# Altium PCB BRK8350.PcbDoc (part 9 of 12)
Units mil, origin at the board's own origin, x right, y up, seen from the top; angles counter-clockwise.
Board outline 9448.82 x 5905.51 mil, 8 copper layers (L1-TOP, L2-GND, L3-SIG, L4-GND, L5-PWR, L6-PWR, L7-GND, L8-BOT), stack 57.69 mil thick; 288 components, 543 nets, 1891 pads, 2032 vias.
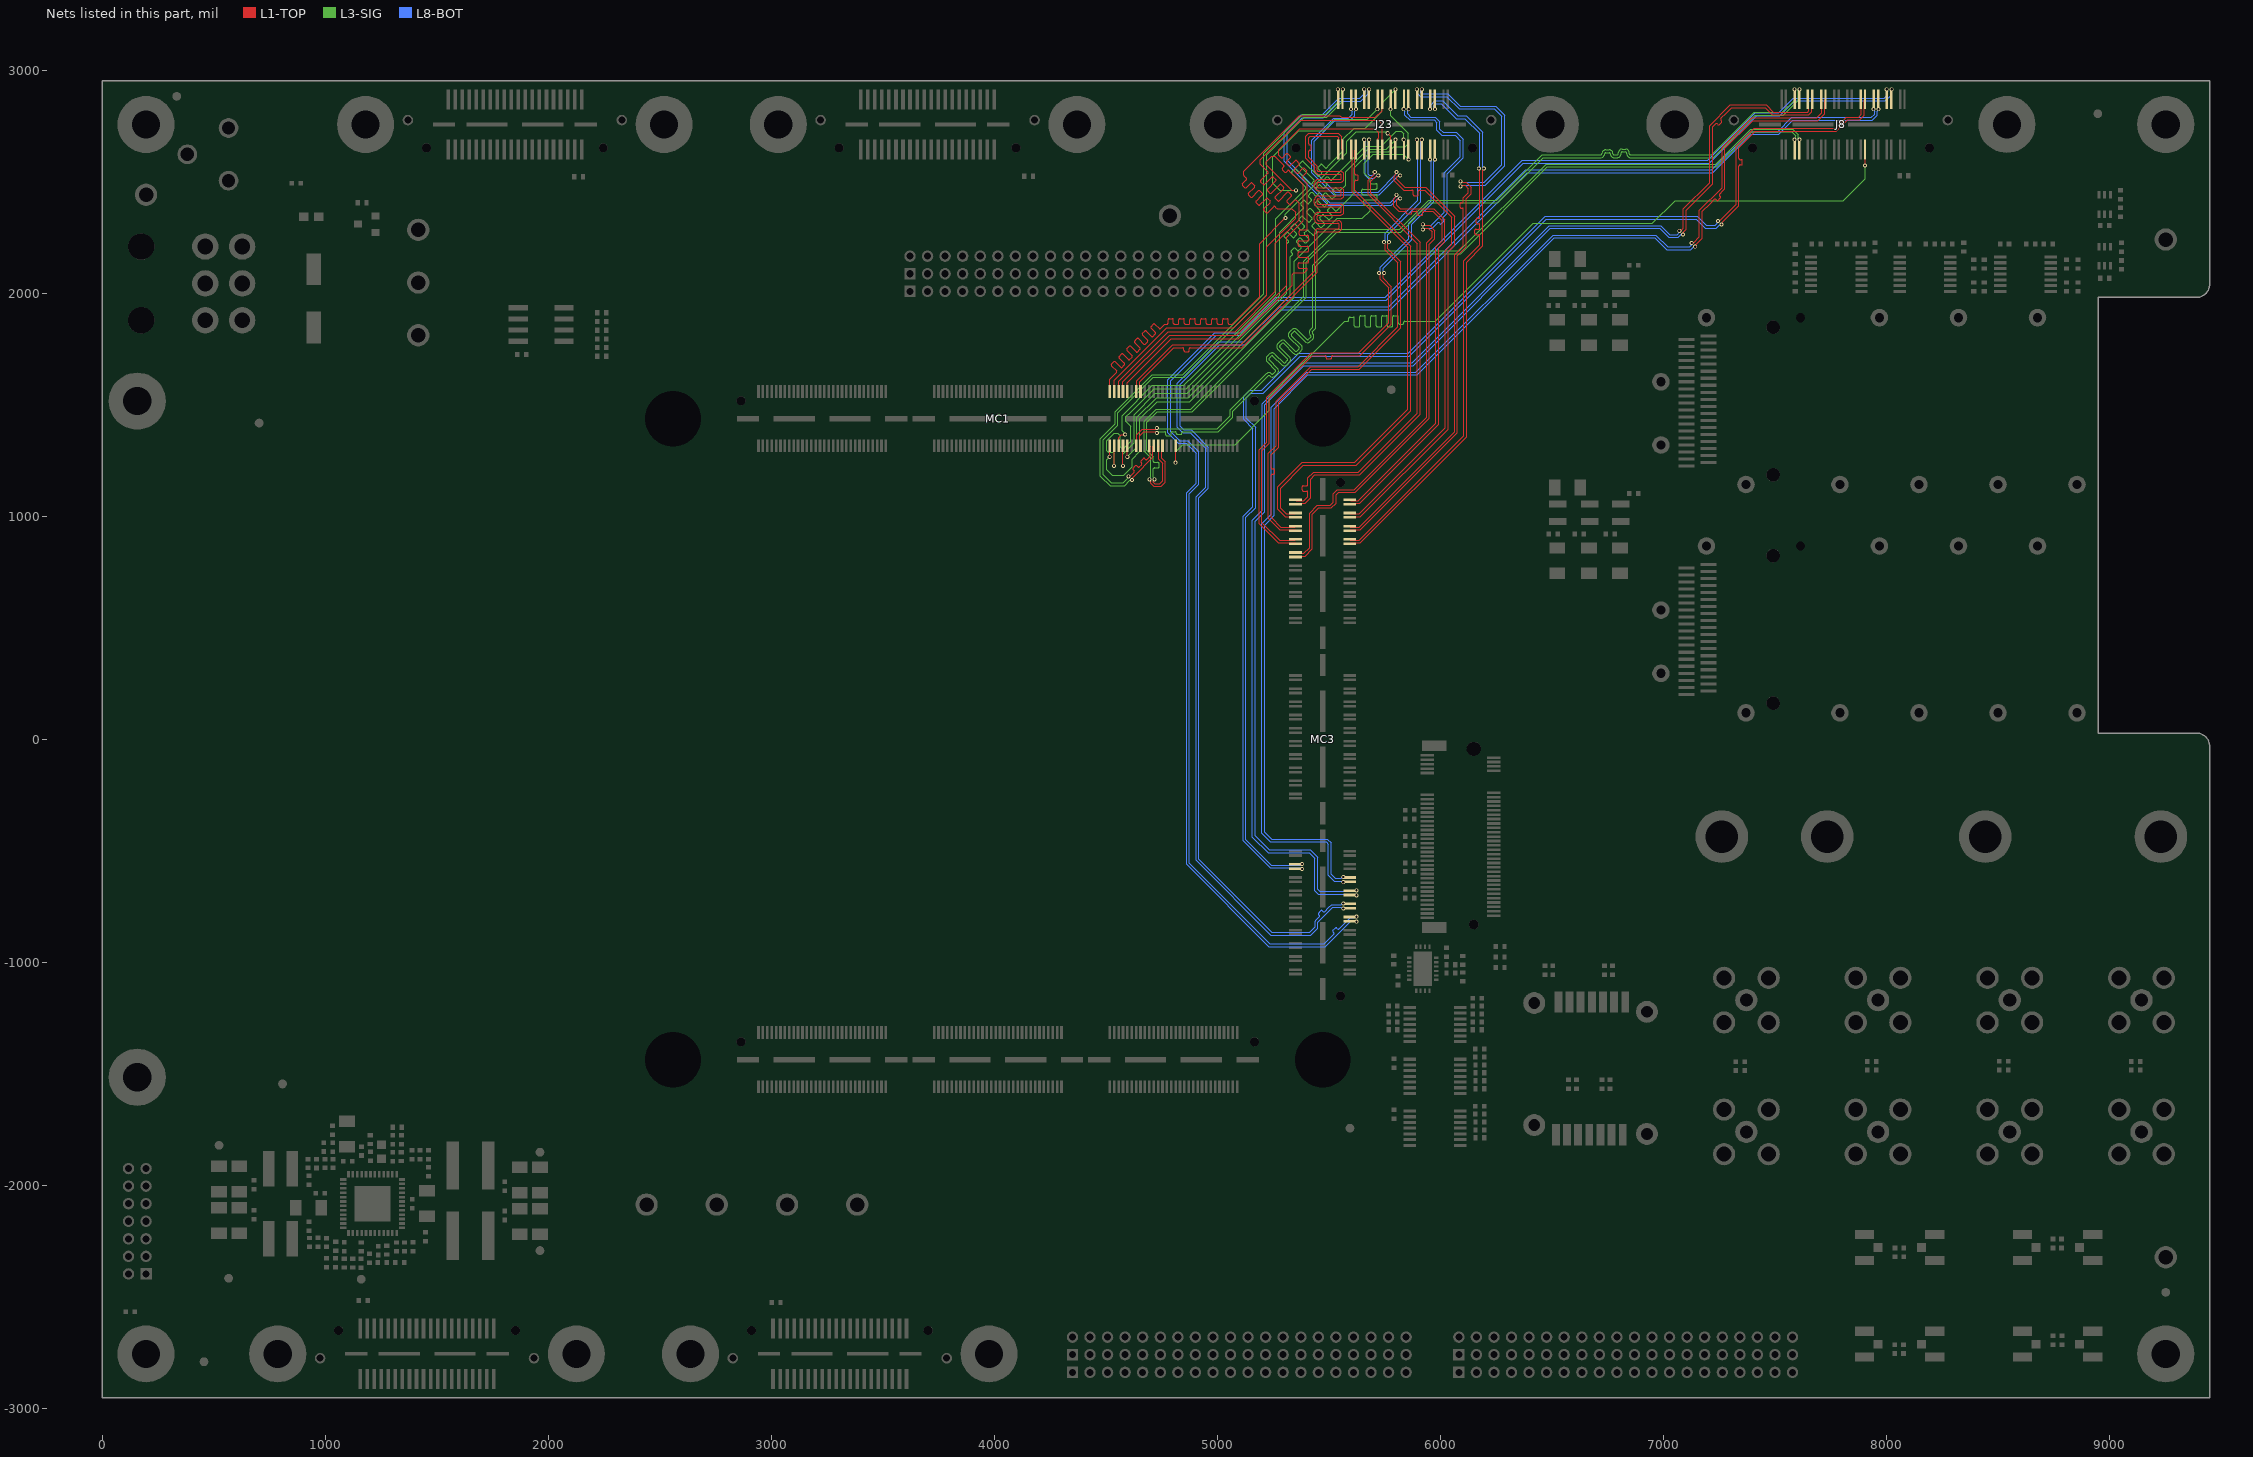
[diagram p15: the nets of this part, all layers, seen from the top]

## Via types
v1: diameter 18, hole 10, L1-TOP to L8-BOT, tented both sides, 2032 vias

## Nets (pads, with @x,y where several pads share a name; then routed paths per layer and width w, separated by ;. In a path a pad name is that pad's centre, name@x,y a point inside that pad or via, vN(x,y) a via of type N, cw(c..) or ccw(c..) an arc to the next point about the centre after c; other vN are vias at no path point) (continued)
PORTE_C2P_CLKN: J23.36 MC1.135 | length 2762.6
  L1-TOP w4.2: MC1.135@4655.53,1558.68 4651.98,1562.22 4651.98,1602.36 4701.98,1652.35 4759.06,1709.44 4804.76,1755.14 4818.81,1755.14 4845.11,1755.14 cw(c4845.11,1750.3) 4849.95,1750.3 4849.95,1742.6 ccw(c4854.79,1742.6) 4854.79,1737.76 4869.31,1737.76 ccw(c4869.31,1742.6) 4874.15,1742.6 4874.15,1750.3 cw(c4878.99,1750.3) 4878.99,1755.14 4895.59,1755.14 5109.74,1755.14 5448.62,2094.02 5448.62,2114.17 5448.62,2270.96 cw(c5453.46,2270.96) 5453.46,2275.8 5540.81,2275.8 ccw(c5540.81,2293.24) 5558.25,2293.24 5558.25,2307.76 ccw(c5540.81,2307.76) 5540.81,2325.2 5452.99,2325.2 cw(c5452.99,2330.04) 5448.15,2330.04 5448.15,2344.56 cw(c5452.99,2344.56) 5452.99,2349.4 5550.27,2349.4 ccw(c5550.27,2366.84) 5567.71,2366.84 5567.71,2381.36 ccw(c5550.27,2381.36) 5550.27,2398.8 5452.99,2398.8 cw(c5452.99,2403.64) 5448.15,2403.64 5448.15,2418.16 cw(c5452.99,2418.16) 5452.99,2423 5550.27,2423 ccw(c5550.27,2440.44) 5567.71,2440.44 5567.71,2454.96 ccw(c5550.27,2454.96) 5550.27,2472.4 5452.99,2472.4 cw(c5452.99,2477.24) 5448.15,2477.24 5448.15,2491.76 cw(c5452.99,2491.76) 5452.99,2496.6 5550.27,2496.6 ccw(c5550.27,2514.04) 5567.71,2514.04 5567.71,2528.56 ccw(c5550.27,2528.56) 5550.27,2546 5453.46,2546 cw(c5453.46,2550.84) 5448.62,2550.84 5448.62,2559.24 5448.62,2569.41 5409.45,2608.58 5409.45,2634.88 cw(c5414.29,2634.88) 5414.29,2639.72 5416.42,2639.72 ccw(c5416.42,2644.56) 5421.26,2644.56 5421.26,2659.08 ccw(c5416.42,2659.08) 5416.42,2663.92 5414.29,2663.92 cw(c5414.29,2668.76) 5409.45,2668.76 5409.45,2689.78 5409.45,2697.27 5415.92,2703.74 5537.2,2703.74 5545.04,2695.91 5545.04,2688.08 5544.91,2687.95 5544.91,2646.44 J23.36@5541.5,2643.03
PORTE_C2P_CLKP: J23.34 MC1.133 | length 2762.6
  L1-TOP w4.2: MC1.133@4635.84,1558.68 4639.38,1562.22 4639.38,1607.58 4799.54,1767.74 5104.52,1767.74 5436.02,2099.24 5436.02,2114.17 5436.02,2270.96 cw(c5453.46,2270.96) 5453.46,2288.4 5540.81,2288.4 ccw(c5540.81,2293.24) 5545.65,2293.24 5545.65,2307.76 ccw(c5540.81,2307.76) 5540.81,2312.6 5452.99,2312.6 cw(c5452.99,2330.04) 5435.55,2330.04 5435.55,2344.56 cw(c5452.99,2344.56) 5452.99,2362 5550.27,2362 ccw(c5550.27,2366.84) 5555.11,2366.84 5555.11,2381.36 ccw(c5550.27,2381.36) 5550.27,2386.2 5452.99,2386.2 cw(c5452.99,2403.64) 5435.55,2403.64 5435.55,2418.16 cw(c5452.99,2418.16) 5452.99,2435.6 5550.27,2435.6 ccw(c5550.27,2440.44) 5555.11,2440.44 5555.11,2454.96 ccw(c5550.27,2454.96) 5550.27,2459.8 5452.99,2459.8 cw(c5452.99,2477.24) 5435.55,2477.24 5435.55,2491.76 cw(c5452.99,2491.76) 5452.99,2509.2 5550.27,2509.2 ccw(c5550.27,2514.04) 5555.11,2514.04 5555.11,2528.56 ccw(c5550.27,2528.56) 5550.27,2533.4 5453.46,2533.4 cw(c5453.46,2550.84) 5436.02,2550.84 5436.02,2559.24 5436.02,2564.19 5396.85,2603.36 5396.85,2702.49 5410.7,2716.34 5542.42,2716.34 5557.64,2701.13 5557.64,2688.08 5557.77,2687.95 5557.77,2646.44 J23.34@5561.18,2643.03
PORTE_P2C_CLKN: J23.35 MC1.142 | length 2684.1
  L1-TOP w4.2: v1(4617.02,1162.51) 4619.66,1165.15 4619.66,1172.15 4628.75,1181.23 4711.04,1263.53 4711.04,1311.83 MC1.142@4714.58,1315.37
  L3-SIG w4.25: v1(4617.02,1162.51) 4614.39,1159.88 4607.43,1159.88 4584.04,1136.49 4518.85,1136.49 4475.54,1179.8 4475.54,1262.21 4475.54,1347.82 4541.34,1413.62 4541.34,1467.81 4687.7,1614.17 4708.37,1634.84 4845.47,1634.84 5208.66,1998.03 5208.66,2625.98 5383.71,2801.04 5421.26,2801.04 5486.08,2801.04 5545.01,2859.97 5545.01,2911.21 5542.52,2913.7 v1(5540.09,2913.7)
PORTE_P2C_CLKP: J23.33 MC1.140 | length 2684.1
  L1-TOP w4.2: v1(4601.11,1178.42) 4603.75,1181.06 4610.75,1181.06 4615.39,1185.69 4625.03,1195.33 4626.51,1196.82 ccw(c4623.09,1200.24) 4626.51,1203.66 4622.36,1207.81 cw(c4625.79,1211.23) 4622.36,1214.65 4632.63,1224.92 cw(c4636.05,1221.5) 4639.48,1224.92 4643.62,1220.77 ccw(c4647.05,1224.19) 4650.47,1220.77 4660.74,1231.04 ccw(c4657.31,1234.46) 4660.74,1237.88 4657.89,1240.73 cw(c4661.31,1244.15) 4657.89,1247.57 4668.16,1257.84 cw(c4671.58,1254.42) 4675,1257.84 4677.85,1255 ccw(c4681.27,1258.42) 4684.69,1255 4691.83,1262.13 4698.44,1268.74 4698.44,1311.83 MC1.140@4694.9,1315.37
  L3-SIG w4.25: v1(4601.11,1178.42) 4598.48,1175.79 4598.48,1168.82 4578.8,1149.14 4524.09,1149.14 4488.19,1185.04 4488.19,1342.58 4553.99,1408.38 4553.99,1462.57 4713.61,1622.19 4850.71,1622.19 5221.31,1992.79 5221.31,2620.74 5388.95,2788.39 5491.31,2788.39 5557.66,2854.73 5557.66,2911.21 5560.15,2913.7 v1(5562.59,2913.7)
PORTE_REFCLKN: J23.15 MC3.20 | length 2706.5
  L1-TOP w4.2: MC3.20@5350.8,816.94 5354.35,820.49 5393.42,820.49 5425.99,853.05 5425.99,1008.66 5453.79,1036.47 5510.98,1036.47 5532.29,1057.77 5532.29,1095.28 5543.31,1106.3 5618.17,1106.3 5950.53,1438.66 5950.53,2219.59 5975.25,2244.31 5975.25,2279.66 5951.76,2303.15 5929.94,2303.15 5924.99,2308.1 v1(5921.26,2308.1)
  L8-BOT w4.2: v1(5835.36,2824.33) 5835.36,2820.6 5840.31,2815.65 5840.31,2797.7 5861.67,2776.35 5971.68,2776.35 5984.25,2763.78 5984.25,2730.21 6006.59,2707.87 6065.65,2707.87 6089.52,2684 6089.52,2611.72 6017.41,2539.62 6017.41,2362 5958.56,2303.15 5929.13,2303.15 5924.18,2308.1 v1(5921.26,2308.1)
PORTE_REFCLKP: J23.13 MC3.18 | length 2706.5
  L1-TOP w4.2: MC3.18@5350.8,836.63 5354.35,833.09 5388.21,833.09 5413.39,858.27 5413.39,1013.88 5448.57,1049.07 5505.76,1049.07 5519.69,1062.99 5519.69,1100.5 5538.09,1118.9 5612.95,1118.9 5937.93,1443.88 5937.93,2224.81 5962.65,2249.53 5962.65,2274.44 5946.54,2290.55 5929.94,2290.55 5924.99,2285.6 v1(5921.26,2285.6)
  L8-BOT w4.2: v1(5857.86,2824.33) 5857.86,2820.6 5852.91,2815.65 5852.91,2802.92 5866.88,2788.95 5976.9,2788.95 5996.85,2769 5996.85,2735.43 6011.81,2720.47 6070.87,2720.47 6102.12,2689.22 6102.12,2606.51 6030.01,2534.4 6030.01,2356.78 6023.6,2350.38 6011.54,2338.31 ccw(c6014.96,2334.89) 6011.54,2331.47 6015.01,2327.99 cw(c6011.59,2324.57) 6015.01,2321.15 6004.75,2310.88 cw(c6001.32,2314.3) 5997.9,2310.88 5994.43,2314.35 ccw(c5991,2310.93) 5987.58,2314.35 5968.99,2295.76 5963.78,2290.55 5929.13,2290.55 5924.18,2285.6 v1(5921.26,2285.6)
PORTE_RX0N: J23.7 MC3.15 | length 2441.1
  L1-TOP w4.2: MC3.15@5594.11,876 5597.65,879.54 5641.57,879.54 6117.73,1355.7 6117.73,2139.28 6189.77,2211.32 6189.77,2413.6 6189.77,2443.03 6189.77,2550.37 6194.72,2555.32 v1(6194.72,2559.06)
  L8-BOT w4.2: v1(5953.47,2824.33) 5953.47,2828.07 5958.42,2833.02 5958.42,2844.85 5975.78,2862.2 6009.95,2862.2 6076.87,2795.28 6115.46,2795.28 6189.77,2720.97 6189.77,2566.93 6194.72,2561.98 v1(6194.72,2559.06)
PORTE_RX0P: J23.5 MC3.13 | length 2441.1
  L1-TOP w4.2: MC3.13@5594.11,895.69 5597.65,892.14 5636.35,892.14 6105.13,1360.92 6105.13,2144.5 6177.17,2216.54 6177.17,2255.36 6177.17,2257.46 ccw(c6172.33,2257.46) 6172.33,2262.3 6159.74,2262.3 cw(c6159.74,2267.14) 6154.9,2267.14 6154.9,2281.66 cw(c6159.74,2281.66) 6159.74,2286.5 6172.33,2286.5 ccw(c6172.33,2291.34) 6177.17,2291.34 6177.17,2305.86 ccw(c6172.33,2305.86) 6172.33,2310.7 6164.65,2310.7 cw(c6164.65,2315.54) 6159.81,2315.54 6159.81,2330.06 cw(c6164.65,2330.06) 6164.65,2334.9 6172.33,2334.9 ccw(c6172.33,2339.74) 6177.17,2339.74 6177.17,2394.9 6177.17,2550.37 6172.22,2555.32 v1(6172.22,2559.06)
  L8-BOT w4.2: v1(5975.97,2824.33) 5975.97,2828.07 5971.02,2833.02 5971.02,2839.63 5981,2849.6 6004.73,2849.6 6071.66,2782.68 6110.24,2782.68 6177.17,2715.75 6177.17,2566.93 6172.22,2561.98 v1(6172.22,2559.06)
PORTE_RX1N: J23.11 MC3.11 | length 2727.3
  L1-TOP w4.2: MC3.11@5594.11,935.06 5597.65,938.6 5641.51,938.6 6075.93,1373.01 6075.93,2167.17 6116.1,2207.35 6116.1,2423.19 6138.58,2445.67 6138.58,2473.72 6116.24,2496.06 6099.24,2496.06 6094.29,2501.01 v1(6090.55,2501.01)
  L8-BOT w4.2: v1(5894.42,2913.7) 5894.42,2909.97 5899.37,2905.02 5899.37,2893.18 5911.45,2881.1 6028.35,2881.1 6083.47,2825.98 6242.18,2825.98 6275.75,2792.41 6275.75,2574.96 6196.85,2496.06 6099.24,2496.06 6094.29,2501.01 v1(6090.55,2501.01)
PORTE_RX1P: J23.9 MC3.9 | length 2727.3
  L1-TOP w4.2: MC3.9@5594.11,954.74 5597.65,951.2 5636.3,951.2 6063.33,1378.23 6063.33,2172.39 6103.5,2212.57 6103.5,2374.02 6103.5,2376.12 ccw(c6098.66,2376.12) 6098.66,2380.96 6093.75,2380.96 cw(c6093.75,2385.8) 6088.91,2385.8 6088.91,2400.32 cw(c6093.75,2400.32) 6093.75,2405.16 6098.66,2405.16 ccw(c6098.66,2410) 6103.5,2410 6103.5,2424.63 6103.5,2428.41 6125.98,2450.89 6125.98,2468.5 6111.03,2483.46 6099.24,2483.46 6094.29,2478.51 v1(6090.55,2478.51)
  L8-BOT w4.2: v1(5916.92,2913.7) 5916.92,2909.97 5911.97,2905.02 5911.97,2898.4 5916.67,2893.7 6033.57,2893.7 6088.69,2838.58 6247.4,2838.58 6288.35,2797.63 6288.35,2569.74 6202.07,2483.46 6099.24,2483.46 6094.29,2478.51 v1(6090.55,2478.51)
PORTE_RX2N: J23.31 MC3.7 | length 2800
  L1-TOP w4.2: MC3.7@5594.11,994.11 5597.65,997.65 5641.46,997.65 6034.13,1390.33 6034.13,2184.49 6063.78,2214.14 6063.78,2345.34 5934.66,2474.46 5840.5,2474.46 5805.18,2509.78 5805.18,2519.64 5809.86,2524.32 5816.86,2524.32 v1(5819.5,2526.96)
  L8-BOT w4.2: v1(5599.14,2824.33) 5599.14,2820.6 5604.09,2815.65 5604.09,2800.94 5587.82,2784.67 5521.68,2784.67 5422.53,2685.52 5422.53,2539.96 5522.34,2440.16 5725.69,2440.16 5812.06,2526.52 5819.06,2526.52 v1(5819.5,2526.96)
PORTE_RX2P: J23.29 MC3.5 | length 2800
  L1-TOP w4.2: MC3.5@5594.11,1013.8 5597.65,1010.25 5636.24,1010.25 6021.53,1395.55 6021.53,2189.71 6051.18,2219.36 6051.18,2340.12 5929.44,2461.86 5908.57,2461.86 5906.47,2461.86 ccw(c5906.47,2457.02) 5901.63,2457.02 5901.63,2441.67 cw(c5896.79,2441.67) 5896.79,2436.83 5882.27,2436.83 cw(c5882.27,2441.67) 5877.43,2441.67 5877.43,2457.02 ccw(c5872.59,2457.02) 5872.59,2461.86 5844.83,2461.86 5835.28,2461.86 5792.58,2504.56 5792.58,2524.86 5800.95,2533.23 5800.95,2540.23 v1(5803.59,2542.87)
  L8-BOT w4.2: v1(5621.64,2824.33) 5621.64,2820.6 5616.69,2815.65 5616.69,2795.72 5593.04,2772.07 5526.9,2772.07 5435.13,2680.3 5435.13,2545.18 5527.56,2452.76 5720.47,2452.76 5803.15,2535.43 5803.15,2542.43 v1(5803.59,2542.87)
PORTE_RX3N: J23.27 MC3.3 | length 2963
  L1-TOP w4.2: MC3.3@5594.11,1053.17 5597.65,1056.71 5637.52,1056.71 5992.33,1411.52 5992.33,2202.28 6020.47,2230.42 6020.47,2329.53 5971.02,2378.99 5819.02,2378.99 5803.4,2394.62 5803.4,2415.5 5809.86,2421.96 5816.86,2421.96 v1(5819.5,2424.6)
  L8-BOT w4.2: v1(5658.2,2913.7) 5658.2,2909.97 5663.15,2905.02 5663.15,2898.4 5637.63,2872.88 5544.31,2872.88 5470.64,2799.21 5375.11,2799.21 5300.51,2724.62 5300.51,2590.18 5498.03,2392.67 5780.56,2392.67 5814.26,2426.36 5817.74,2426.36 v1(5819.5,2424.6)
PORTE_RX3P: J23.25 MC3.1 | length 2963
  L1-TOP w4.2: MC3.1@5594.11,1072.85 5597.65,1069.31 5632.3,1069.31 5979.73,1416.74 5979.73,2207.5 6007.87,2235.64 6007.87,2324.31 5965.8,2366.39 5927.03,2366.39 5924.93,2366.39 ccw(c5924.93,2361.55) 5920.09,2361.55 5920.09,2353.67 cw(c5915.25,2353.67) 5915.25,2348.83 5900.73,2348.83 cw(c5900.73,2353.67) 5895.89,2353.67 5895.89,2361.55 ccw(c5891.05,2361.55) 5891.05,2366.39 5876.53,2366.39 ccw(c5876.53,2361.55) 5871.69,2361.55 5871.69,2359.6 cw(c5866.85,2359.6) 5866.85,2354.76 5852.33,2354.76 cw(c5852.33,2359.6) 5847.49,2359.6 5847.49,2361.55 ccw(c5842.65,2361.55) 5842.65,2366.39 5819.02,2366.39 5813.81,2366.39 5790.8,2389.4 5790.8,2420.72 5800.95,2430.87 5800.95,2437.87 v1(5803.59,2440.51)
  L8-BOT w4.2: v1(5680.7,2913.7) 5680.7,2909.97 5675.75,2905.02 5675.75,2893.18 5642.85,2860.28 5549.53,2860.28 5475.86,2786.61 5380.33,2786.61 5313.11,2719.4 5313.11,2595.4 5503.25,2405.27 5775.34,2405.27 5805.35,2435.27 5803.59,2437.03 v1(5803.59,2440.51)
PORTE_S0: J23.14 MC1.122 | length 2681
  L1-TOP w4.5: v1(4517.53,1265.67) 4517.63,1265.77 4517.63,1315.27 MC1.122@4517.73,1315.37
  L3-SIG w4.6: v1(4517.53,1265.67) 4503.94,1252.07 4503.94,1207.13 4528.96,1182.11 4579.63,1182.11 4618.11,1220.6 4618.11,1255.02 4653.07,1289.98 4653.07,1435.83 4731.02,1513.78 4876.3,1513.78 5344.48,1981.96 5344.48,2141.96 5537.16,2334.65 5649.61,2334.65 5685.04,2370.08 5685.04,2377.95 5685.04,2387.82 ccw(c5680.12,2387.82) 5680.12,2392.74 5660.55,2392.74 cw(c5660.55,2397.66) 5655.63,2397.66 5655.63,2412.42 cw(c5660.55,2412.42) 5660.55,2417.34 5711.1,2417.34 ccw(c5711.1,2422.26) 5716.02,2422.26 5716.02,2437.02 ccw(c5711.1,2437.02) 5711.1,2441.94 5652.86,2441.94 cw(c5652.86,2446.86) 5647.94,2446.86 5647.94,2461.62 cw(c5652.86,2461.62) 5652.86,2466.54 5711.1,2466.54 ccw(c5711.1,2471.46) 5716.02,2471.46 5716.02,2486.22 ccw(c5711.1,2486.22) 5711.1,2491.14 5689.96,2491.14 cw(c5689.96,2496.06) 5685.04,2496.06 5685.04,2498.36 5685.04,2511.81 5658.62,2538.23 5658.62,2581.85 5698.72,2621.94 5834.26,2621.94 v1(5857.86,2598.35)
PORTE_S1: J23.16 MC1.124 | length 2681.2
  L1-TOP w4.5: v1(4537.09,1225.55) 4537.25,1225.72 4537.25,1315.21 MC1.124@4537.42,1315.37
  L3-SIG w4.6: v1(4537.09,1225.55) 4537.09,1280.97 4530.65,1287.4 4510.31,1287.4 4503.94,1293.77 4503.94,1338.58 4537.29,1371.93 4553.26,1371.93 4564.66,1360.54 4564.66,1310.79 4570.56,1304.89 4579.5,1304.89 4611.26,1336.65 4611.26,1403.02 4590.06,1424.21 4590.06,1444.54 4611.26,1465.73 4716.39,1570.87 4860.24,1570.87 4923.23,1633.86 5279.53,1990.16 5279.53,2273.18 5383.53,2377.19 5385.16,2378.81 ccw(c5381.68,2382.29) 5385.16,2385.77 5374.44,2396.49 cw(c5377.92,2399.97) 5374.44,2403.45 5384.87,2413.89 cw(c5388.35,2410.41) 5391.83,2413.89 5403.33,2402.39 ccw(c5406.81,2405.87) 5410.28,2402.39 5420.72,2412.83 ccw(c5417.24,2416.31) 5420.72,2419.78 5409.23,2431.28 cw(c5412.71,2434.76) 5409.23,2438.24 5419.66,2448.67 cw(c5423.14,2445.2) 5426.62,2448.67 5438.12,2437.18 ccw(c5441.6,2440.66) 5445.07,2437.18 5455.51,2447.62 ccw(c5452.03,2451.1) 5455.51,2454.57 5444.02,2466.07 cw(c5447.5,2469.55) 5444.02,2473.03 5454.45,2483.46 cw(c5457.93,2479.99) 5461.41,2483.46 5472.91,2471.97 ccw(c5476.38,2475.45) 5479.86,2471.97 5490.3,2482.41 ccw(c5486.82,2485.89) 5490.3,2489.36 5478.81,2500.86 cw(c5482.28,2504.34) 5478.81,2507.82 5489.24,2518.25 cw(c5492.72,2514.78) 5496.2,2518.25 5506.92,2507.53 ccw(c5510.4,2511.01) 5513.88,2507.53 5556.36,2550.02 5663.5,2657.16 5734.82,2657.16 5802.65,2724.99 5823.61,2724.99 5834.89,2713.71 5834.89,2696.81 5835.36,2696.34 v1(5835.36,2687.72)
PORTE_S2: J23.17 MC1.126 | length 2680.7
  L1-TOP w4.5: MC1.126@4557.1,1315.37 4557.1,1351.57 4569.95,1364.43 4584.9,1364.43 v1(4586.61,1366.14)
  L3-SIG w4.6: v1(4586.61,1366.14) 4586.61,1369.63 4572.83,1383.41 4572.83,1450.93 4708.52,1586.61 4850.39,1586.61 4897.64,1633.86 5261.43,1997.65 5261.43,2333.28 5394.36,2466.21 5395.99,2467.84 ccw(c5392.51,2471.31) 5395.99,2474.79 5333.68,2537.1 cw(c5337.16,2540.58) 5333.68,2544.06 5344.11,2554.5 cw(c5347.59,2551.02) 5351.07,2554.5 5415.28,2490.29 ccw(c5418.76,2493.77) 5422.23,2490.29 5432.67,2500.73 ccw(c5429.19,2504.21) 5432.67,2507.69 5368.47,2571.89 cw(c5371.95,2575.37) 5368.47,2578.85 5378.9,2589.29 cw(c5382.38,2585.81) 5385.86,2589.29 5450.07,2525.08 ccw(c5453.55,2528.56) 5457.02,2525.08 5467.46,2535.52 ccw(c5463.98,2539) 5467.46,2542.48 5452.07,2557.87 cw(c5455.55,2561.35) 5452.07,2564.82 5462.51,2575.26 cw(c5465.99,2571.78) 5469.47,2575.26 5482.96,2561.77 ccw(c5486.44,2565.25) 5489.92,2561.77 5502.48,2574.33 5562.99,2634.84 5562.99,2688.91 5612.65,2738.57 5663.42,2738.57 5737.25,2812.4 5737.25,2852.14 v1(5798.81,2913.7)
PORTE_S3: J23.18 MC1.128 | length 2681
  L1-TOP w4.5: v1(4576.46,1225.55) 4576.62,1225.72 4576.62,1315.21 MC1.128@4576.79,1315.37
  L3-SIG w4.6: v1(4576.46,1225.55) 4576.46,1277.35 4626.96,1327.85 4626.96,1455.57 4722.58,1551.18 4864.03,1551.18 5311.28,1998.43 5311.28,2220.73 5316.47,2225.92 5318.1,2227.55 ccw(c5314.62,2231.03) 5318.1,2234.51 5299.61,2253 cw(c5303.09,2256.48) 5299.61,2259.96 5310.04,2270.4 cw(c5313.52,2266.92) 5317,2270.4 5337.26,2250.13 ccw(c5340.74,2253.61) 5344.22,2250.13 5354.66,2260.57 ccw(c5351.18,2264.05) 5354.66,2267.53 5331.55,2290.63 cw(c5335.03,2294.11) 5331.55,2297.59 5341.99,2308.03 cw(c5345.47,2304.55) 5348.95,2308.03 5372.05,2284.92 ccw(c5375.53,2288.4) 5379.01,2284.92 5389.45,2295.36 ccw(c5385.97,2298.84) 5389.45,2302.32 5366.34,2325.42 cw(c5369.82,2328.9) 5366.34,2332.38 5376.78,2342.82 cw(c5380.26,2339.34) 5383.74,2342.82 5406.84,2319.71 ccw(c5410.32,2323.19) 5413.8,2319.71 5424.24,2330.15 ccw(c5420.76,2333.63) 5424.24,2337.11 5401.13,2360.21 cw(c5404.61,2363.69) 5401.13,2367.17 5411.57,2377.61 cw(c5415.05,2374.13) 5418.53,2377.61 5441.63,2354.5 ccw(c5445.11,2357.98) 5448.59,2354.5 5459.03,2364.94 ccw(c5455.55,2368.42) 5459.03,2371.9 5435.92,2395 cw(c5439.4,2398.48) 5435.92,2401.96 5446.36,2412.4 cw(c5449.84,2408.92) 5453.32,2412.4 5476.42,2389.29 ccw(c5479.9,2392.77) 5483.38,2389.29 5493.82,2399.73 ccw(c5490.34,2403.21) 5493.82,2406.69 5470.71,2429.79 cw(c5474.19,2433.27) 5470.71,2436.75 5481.15,2447.19 cw(c5484.63,2443.71) 5488.11,2447.19 5511.21,2424.08 ccw(c5514.69,2427.56) 5518.17,2424.08 5528.61,2434.52 ccw(c5525.13,2438) 5528.61,2441.48 5516.44,2453.64 cw(c5519.92,2457.12) 5516.44,2460.6 5526.88,2471.04 cw(c5530.36,2467.56) 5533.84,2471.04 5544.23,2460.64 ccw(c5547.71,2464.12) 5551.19,2460.64 5574.8,2484.25 5574.8,2487.45 5574.8,2544.98 5675.24,2645.42 5756.51,2645.42 v1(5798.81,2687.72)
PORTE_S4: J23.19 MC1.130 | length 2679.5
  L1-TOP w4.5: v1(4596.27,1265.67) 4596.37,1265.77 4596.37,1315.27 MC1.130@4596.47,1315.37
  L3-SIG w4.6: v1(4596.27,1265.67) 4639.64,1309.04 4639.64,1442.93 4728.2,1531.5 4868.85,1531.5 5327.88,1990.52 5327.88,2162.52 5334.65,2169.29 5336.27,2170.92 ccw(c5332.79,2174.4) 5336.27,2177.88 5331.36,2182.79 cw(c5334.84,2186.27) 5331.36,2189.75 5341.79,2200.19 cw(c5345.27,2196.71) 5348.75,2200.19 5357.8,2191.14 ccw(c5361.28,2194.62) 5364.76,2191.14 5375.2,2201.57 ccw(c5371.72,2205.05) 5375.2,2208.53 5355.79,2227.94 cw(c5359.27,2231.42) 5355.79,2234.9 5366.22,2245.33 cw(c5369.7,2241.86) 5373.18,2245.33 5392.59,2225.93 ccw(c5396.07,2229.41) 5399.55,2225.93 5409.99,2236.36 ccw(c5406.51,2239.84) 5409.99,2243.32 5390.58,2262.73 cw(c5394.06,2266.21) 5390.58,2269.69 5401.01,2280.12 cw(c5404.49,2276.64) 5407.97,2280.12 5427.38,2260.72 ccw(c5430.86,2264.2) 5434.34,2260.72 5444.77,2271.15 ccw(c5441.3,2274.63) 5444.77,2278.11 5425.37,2297.52 cw(c5428.85,2301) 5425.37,2304.48 5435.8,2314.91 cw(c5439.28,2311.43) 5442.76,2314.91 5462.17,2295.51 ccw(c5465.65,2298.98) 5469.13,2295.51 5479.56,2305.94 ccw(c5476.09,2309.42) 5479.56,2312.9 5460.16,2332.31 cw(c5463.64,2335.79) 5460.16,2339.27 5470.59,2349.7 cw(c5474.07,2346.22) 5477.55,2349.7 5496.96,2330.3 ccw(c5500.44,2333.77) 5503.92,2330.3 5514.35,2340.73 ccw(c5510.88,2344.21) 5514.35,2347.69 5494.95,2367.1 cw(c5498.43,2370.58) 5494.95,2374.06 5505.38,2384.49 cw(c5508.86,2381.01) 5512.34,2384.49 5527.62,2369.22 ccw(c5531.09,2372.7) 5534.57,2369.22 5588.42,2423.07 5614.17,2448.82 5614.17,2560.88 5686.98,2633.68 5768.25,2633.68 5791.1,2656.53 5842.74,2656.53 5856.3,2670.09 5856.3,2715.91 5776.31,2795.9 v1(5776.31,2824.33)
PORTE_S5: J23.20 MC1.121 | length 2725.7
  L1-TOP w4.5: MC1.121@4517.73,1558.68 4517.73,1614.17 4546.27,1642.71 4547.86,1644.3 ccw(c4544.39,1647.76) 4547.86,1651.23 4525.2,1673.89 cw(c4528.67,1677.35) 4525.2,1680.82 4535.6,1691.21 cw(c4539.06,1687.75) 4542.53,1691.21 4566.11,1667.63 ccw(c4569.58,1671.09) 4573.04,1667.63 4583.44,1678.02 ccw(c4579.97,1681.49) 4583.43,1684.95 4559.85,1708.53 cw(c4563.32,1712) 4559.85,1715.46 4570.24,1725.86 cw(c4573.71,1722.39) 4577.17,1725.86 4600.76,1702.27 ccw(c4604.22,1705.74) 4607.69,1702.27 4618.08,1712.67 ccw(c4614.62,1716.13) 4618.08,1719.6 4594.5,1743.18 cw(c4597.96,1746.65) 4594.5,1750.11 4604.89,1760.51 cw(c4608.36,1757.04) 4611.82,1760.51 4635.41,1736.92 ccw(c4638.87,1740.39) 4642.34,1736.92 4652.73,1747.32 ccw(c4649.27,1750.78) 4652.73,1754.25 4629.15,1777.83 cw(c4632.61,1781.3) 4629.15,1784.76 4639.54,1795.15 cw(c4643.01,1791.69) 4646.47,1795.15 4670.06,1771.57 ccw(c4673.52,1775.04) 4676.99,1771.57 4687.38,1781.97 ccw(c4683.91,1785.43) 4687.38,1788.89 4663.8,1812.48 cw(c4667.26,1815.94) 4663.8,1819.41 4674.19,1829.8 cw(c4677.65,1826.34) 4681.12,1829.8 4704.7,1806.22 ccw(c4708.17,1809.68) 4711.63,1806.22 4722.03,1816.61 ccw(c4718.56,1820.08) 4722.03,1823.54 4702.69,1842.88 cw(c4706.16,1846.34) 4702.69,1849.81 4713.09,1860.2 cw(c4716.55,1856.74) 4720.02,1860.2 4738.42,1841.79 ccw(c4741.89,1845.26) 4745.35,1841.79 4756.9,1853.34 4763.8,1860.24 4771.65,1860.24 4773.9,1860.24 ccw(c4773.9,1865.14) 4778.8,1865.14 4778.8,1880.34 cw(c4783.7,1880.34) 4783.7,1885.24 4798.4,1885.24 cw(c4798.4,1880.34) 4803.3,1880.34 4803.3,1865.14 ccw(c4808.2,1865.14) 4808.2,1860.24 4822.9,1860.24 ccw(c4822.9,1865.14) 4827.8,1865.14 4827.8,1880.34 cw(c4832.7,1880.34) 4832.7,1885.24 4847.4,1885.24 cw(c4847.4,1880.34) 4852.3,1880.34 4852.3,1865.14 ccw(c4857.2,1865.14) 4857.2,1860.24 4871.9,1860.24 ccw(c4871.9,1865.14) 4876.8,1865.14 4876.8,1880.34 cw(c4881.7,1880.34) 4881.7,1885.24 4896.4,1885.24 cw(c4896.4,1880.34) 4901.3,1880.34 4901.3,1865.14 ccw(c4906.2,1865.14) 4906.2,1860.24 4920.9,1860.24 ccw(c4920.9,1865.14) 4925.8,1865.14 4925.8,1880.34 cw(c4930.7,1880.34) 4930.7,1885.24 4945.4,1885.24 cw(c4945.4,1880.34) 4950.3,1880.34 4950.3,1865.14 ccw(c4955.2,1865.14) 4955.2,1860.24 4969.9,1860.24 ccw(c4969.9,1865.14) 4974.8,1865.14 4974.8,1880.34 cw(c4979.7,1880.34) 4979.7,1885.24 4994.4,1885.24 cw(c4994.4,1880.34) 4999.3,1880.34 4999.3,1865.14 ccw(c5004.2,1865.14) 5004.2,1860.24 5018.9,1860.24 ccw(c5018.9,1865.14) 5023.8,1865.14 5023.8,1880.34 cw(c5028.7,1880.34) 5028.7,1885.24 5043.4,1885.24 cw(c5043.4,1880.34) 5048.3,1880.34 5048.3,1865.14 ccw(c5053.2,1865.14) 5053.2,1860.24 5066.11,1860.24 5070.87,1864.99 5188.98,1983.1 5188.98,2220.47 v1(5305.12,2336.61) ; v1(5763.78,2716.54) 5777.72,2702.6 J23.20@5777.72,2643.03
  L3-SIG w4.6: v1(5305.12,2336.61) 5305.12,2353.49 5579.72,2628.1 5579.72,2681.03 5622.5,2723.81 5755.07,2723.81 5762.34,2716.54 v1(5763.78,2716.54)
PORTE_S6: J23.21 MC1.123 | length 2758.5
  L1-TOP w4.5: MC1.123@4537.42,1558.68 4537.42,1608.67 4772.49,1843.74 5072.95,1843.74 5220.47,1991.26 5220.47,2206.56 5350.44,2336.53 5350.44,2362.16 5334.65,2377.95 5267.72,2377.95 5260.3,2385.37 5258.71,2386.96 ccw(c5255.25,2383.49) 5251.78,2386.96 5225.53,2360.71 cw(c5222.07,2364.17) 5218.6,2360.71 5208.21,2371.1 cw(c5211.67,2374.57) 5208.21,2378.03 5236.17,2405.99 ccw(c5232.7,2409.46) 5236.17,2412.92 5225.77,2423.31 ccw(c5222.31,2419.85) 5218.84,2423.31 5190.88,2395.35 cw(c5187.42,2398.82) 5183.95,2395.35 5173.56,2405.75 cw(c5177.02,2409.21) 5173.56,2412.68 5201.52,2440.64 ccw(c5198.05,2444.1) 5201.52,2447.57 5191.12,2457.96 ccw(c5187.66,2454.5) 5184.19,2457.96 5156.23,2430 cw(c5152.77,2433.47) 5149.3,2430 5138.91,2440.4 cw(c5142.37,2443.86) 5138.91,2447.33 5166.87,2475.29 ccw(c5163.4,2478.75) 5166.87,2482.22 5156.47,2492.61 ccw(c5153.01,2489.15) 5149.55,2492.61 5130.02,2473.09 cw(c5126.56,2476.55) 5123.09,2473.09 5112.7,2483.48 cw(c5116.16,2486.95) 5112.7,2490.41 5130.51,2508.23 ccw(c5127.05,2511.69) 5130.51,2515.16 5119.17,2526.5 5118.11,2527.56 5118.11,2528.62 5118.11,2545.28 5367.84,2795.01 5549.62,2795.01 5557.23,2787.4 5709,2787.4 5738.35,2816.75 J23.21@5738.35,2869.02
PORTE_S7: J23.22 MC1.125 | length 2758.5
  L1-TOP w4.5: MC1.125@4557.1,1558.68 4557.1,1605.02 4779.32,1827.24 5079.78,1827.24 5259.84,2007.3 5259.84,2222.6 5366.94,2329.7 5366.94,2402.74 5355.97,2413.72 5354.38,2415.31 ccw(c5350.91,2411.84) 5347.45,2415.31 5330.06,2397.92 cw(c5326.6,2401.38) 5323.13,2397.92 5312.74,2408.31 cw(c5316.2,2411.78) 5312.74,2415.24 5331.25,2433.76 ccw(c5327.79,2437.22) 5331.25,2440.69 5320.86,2451.08 ccw(c5317.39,2447.62) 5313.93,2451.08 5276.85,2414.01 cw(c5273.39,2417.47) 5269.92,2414.01 5259.53,2424.4 cw(c5262.99,2427.87) 5259.53,2431.33 5296.6,2468.41 ccw(c5293.14,2471.87) 5296.6,2475.34 5286.21,2485.73 ccw(c5282.75,2482.27) 5279.28,2485.73 5242.21,2448.66 cw(c5238.74,2452.12) 5235.28,2448.66 5224.88,2459.05 cw(c5228.35,2462.52) 5224.88,2465.98 5261.96,2503.05 ccw(c5258.49,2506.52) 5261.96,2509.98 5251.56,2520.38 ccw(c5248.1,2516.91) 5244.63,2520.38 5211.76,2487.51 cw(c5208.29,2490.97) 5204.83,2487.51 5194.44,2497.9 cw(c5197.9,2501.36) 5194.44,2504.83 5226.18,2536.58 ccw(c5222.72,2540.04) 5226.18,2543.5 5198.29,2571.39 5196.7,2572.99 5192.91,2576.77 5192.91,2596.74 5370.78,2774.61 5720.47,2774.61 5738.35,2756.73 J23.22@5738.35,2643.03
PORTE_S8: J23.23 MC1.127 | length 2680.9
  L1-TOP w4.5: MC1.127@4576.79,1558.68 4576.79,1601.37 4786.15,1810.74 5086.61,1810.74 5311.02,2035.15 5311.02,2250.44 5385.65,2325.07 5385.65,2484.72 5362.35,2508.02 5323.31,2547.06 5321.72,2548.65 ccw(c5318.25,2545.18) 5314.79,2548.65 5308.9,2542.76 cw(c5305.44,2546.22) 5301.97,2542.76 5291.58,2553.15 cw(c5295.04,2556.62) 5291.58,2560.08 5297.47,2565.97 ccw(c5294,2569.44) 5297.47,2572.9 5277.18,2593.18 5275.59,2594.78 5259.99,2610.38 5257.9,2612.47 5243.82,2612.47 5220.2,2588.84 5220.2,2575.08 5334.65,2460.63 v1(5352.36,2460.63)
  L3-SIG w4.6: v1(5352.36,2460.63) 5279.53,2460.63 5248.03,2492.13 5248.03,2612.18 5364.2,2728.35 5421.26,2728.35 5476.35,2728.35 5526.27,2778.27 5671.19,2778.27 v1(5717.25,2824.33)
PORTE_S9: J23.24 MC1.129 | length 2758.5
  L1-TOP w4.5: MC1.129@4596.47,1558.68 4596.47,1596.85 4793.85,1794.24 5093.45,1794.24 5335.3,2036.09 5335.3,2082.68 5343.17,2090.55 5389.76,2090.55 5403.57,2104.35 5403.57,2106.6 ccw(c5398.66,2106.6) 5398.66,2111.5 5367.75,2111.5 cw(c5367.75,2116.4) 5362.85,2116.4 5362.85,2131.1 cw(c5367.75,2131.1) 5367.75,2136 5403.99,2136 ccw(c5403.99,2140.9) 5408.89,2140.9 5408.89,2155.6 ccw(c5403.99,2155.6) 5403.99,2160.5 5367.75,2160.5 cw(c5367.75,2165.4) 5362.85,2165.4 5362.85,2180.1 cw(c5367.75,2180.1) 5367.75,2185 5403.99,2185 ccw(c5403.99,2189.9) 5408.89,2189.9 5408.89,2204.6 ccw(c5403.99,2204.6) 5403.99,2209.5 5367.75,2209.5 cw(c5367.75,2214.4) 5362.85,2214.4 5362.85,2229.1 cw(c5367.75,2229.1) 5367.75,2234 5403.99,2234 ccw(c5403.99,2238.9) 5408.89,2238.9 5408.89,2253.6 ccw(c5403.99,2253.6) 5403.99,2258.5 5371.82,2258.5 cw(c5371.82,2263.4) 5366.92,2263.4 5366.92,2278.1 cw(c5371.82,2278.1) 5371.82,2283 5398.66,2283 ccw(c5398.66,2287.9) 5403.56,2287.9 5403.57,2312.6 5403.57,2490.14 5398.78,2494.92 5397.19,2496.51 5379.87,2513.83 cw(c5383.33,2517.3) 5379.87,2520.76 5400.47,2541.36 ccw(c5397.01,2544.83) 5400.47,2548.29 5390.08,2558.69 ccw(c5386.61,2555.22) 5383.15,2558.69 5362.55,2538.09 cw(c5359.08,2541.55) 5355.62,2538.09 5345.22,2548.48 cw(c5348.69,2551.94) 5345.22,2555.41 5365.82,2576.01 ccw(c5362.36,2579.47) 5365.82,2582.94 5355.43,2593.33 ccw(c5351.96,2589.87) 5348.5,2593.33 5327.9,2572.73 cw(c5324.43,2576.2) 5320.97,2572.73 5310.57,2583.13 cw(c5314.04,2586.59) 5310.57,2590.06 5326.8,2606.29 ccw(c5323.34,2609.75) 5326.8,2613.22 5316.41,2623.61 ccw(c5312.94,2620.15) 5309.48,2623.61 5293.25,2607.38 cw(c5289.78,2610.85) 5286.32,2607.38 5275.59,2618.11 5275.59,2640.29 5275.59,2642.72 5369.65,2736.78 5705.15,2736.78 5724.17,2717.76 5724.17,2696.81 5718.66,2691.3 J23.24@5718.66,2643.03
PORTE_TX0N: J23.8 MC3.16 | length 2314.5
  L1-TOP w4.2: MC3.16@5350.8,876 5347.26,879.54 5273.52,879.54 5187.26,965.8 5187.26,1298.35 5221.19,1332.27 5221.19,1532.27 5421.2,1732.28 5633.86,1732.28 5767.72,1866.14 5767.72,2024.16 5730.22,2061.66 5730.22,2082.68 5725.27,2087.63 v1(5725.27,2090.11)
  L8-BOT w4.2: v1(5725.27,2090.11) 5725.27,2093.84 5730.22,2098.79 5730.22,2115.94 5858.27,2243.99 5858.27,2313.98 5958.42,2414.14 5958.42,2589.66 5953.47,2594.61 v1(5953.47,2598.35)
PORTE_TX0P: J23.6 MC3.14 | length 2319.7
  L1-TOP w4.2: MC3.14@5350.8,895.69 5347.26,892.14 5278.74,892.14 5199.86,971.02 5199.86,1293.13 5233.79,1327.06 5233.79,1527.05 5426.42,1719.68 5456.69,1719.68 5482.99,1719.68 cw(c5482.99,1714.84) 5487.83,1714.84 5487.83,1709.93 ccw(c5492.67,1709.93) 5492.67,1705.09 5507.19,1705.09 ccw(c5507.19,1709.93) 5512.03,1709.93 5512.03,1714.84 cw(c5516.87,1714.84) 5516.87,1719.68 5551.18,1719.68 5639.08,1719.68 5780.32,1860.92 5780.32,2015.75 ; v1(5747.77,2090.11) 5747.77,2087.63 5742.82,2082.68 5742.82,2066.88 5780.32,2029.38 5780.32,2020.97 ; 5780.32,2015.75 5780.32,2020.97 ; 5780.32,2015.75 5780.32,2020.97
  L8-BOT w4.2: v1(5747.77,2090.11) 5747.77,2093.84 5742.82,2098.79 5742.82,2110.72 5870.87,2238.77 5870.87,2308.76 5971.02,2408.92 5971.02,2589.66 5975.97,2594.61 v1(5975.97,2598.35)
PORTE_TX1N: J23.12 MC3.12 | length 2298.6
  L1-TOP w4.2: MC3.12@5350.8,935.06 5347.26,938.6 5279.8,938.6 5229.06,989.34 5229.06,1244.09 5229.06,1281.03 5262.99,1314.96 5262.99,1514.96 5418.73,1670.7 5631.39,1670.7 5809.52,1848.83 5809.52,2135.37 5751.97,2192.91 5751.97,2219.66 5747.02,2224.61 v1(5747.02,2228.35)
  L8-BOT w4.2: v1(5747.02,2228.35) 5747.02,2231.27 5751.97,2236.22 5751.97,2267.72 5899.37,2415.12 5899.37,2679.03 5894.42,2683.98 v1(5894.42,2687.72)
PORTE_TX1P: J23.10 MC3.10 | length 2298.6
  L1-TOP w4.2: MC3.10@5350.8,954.74 5347.26,951.2 5285.02,951.2 5241.66,994.56 5241.66,1156.09 5241.66,1182.39 cw(c5246.5,1182.39) 5246.5,1187.23 5251.42,1187.23 ccw(c5251.42,1192.07) 5256.26,1192.07 5256.26,1206.59 ccw(c5251.42,1206.59) 5251.42,1211.43 5246.5,1211.43 cw(c5246.5,1216.27) 5241.66,1216.27 5241.66,1244.09 5241.66,1275.82 5275.59,1309.74 5275.59,1509.74 5423.95,1658.1 5636.61,1658.1 5822.12,1843.61 5822.12,2108.66 5822.12,2140.58 5764.57,2198.13 5764.57,2219.66 5769.52,2224.61 v1(5769.52,2228.35)
  L8-BOT w4.2: v1(5769.52,2228.35) 5769.52,2231.27 5764.57,2236.22 5764.57,2262.5 5911.97,2409.9 5911.97,2679.03 5916.92,2683.98 v1(5916.92,2687.72)
PORTE_TX2N: J23.32 MC3.8 | length 2192.8
  L1-TOP w4.2: MC3.8@5350.8,994.11 5347.26,997.65 5303.43,997.65 5270.86,1030.21 5270.86,1131.2 5380.61,1240.95 5616.77,1240.95 5854.33,1478.51 5854.33,2204.72 5604.09,2454.96 5604.09,2586.83 5604.09,2597.99 5603.96,2598.12 5603.96,2639.62 J23.32@5600.55,2643.03
PORTE_TX2P: J23.30 MC3.6 | length 2192.8
  L1-TOP w4.2: MC3.6@5350.8,1013.8 5347.26,1010.25 5308.65,1010.25 5283.46,1035.43 5283.46,1125.98 5385.83,1228.35 5621.99,1228.35 5866.93,1473.29 5866.93,2109.74 5866.93,2209.94 5616.69,2460.18 5616.69,2474.19 5616.69,2500.49 cw(c5621.53,2500.49) 5621.53,2505.33 5626.45,2505.33 ccw(c5626.45,2510.17) 5631.29,2510.17 5631.29,2524.69 ccw(c5626.45,2524.69) 5626.45,2529.53 5621.53,2529.53 cw(c5621.53,2534.37) 5616.69,2534.37 5616.69,2566.93 5616.69,2592.05 5616.69,2597.99 5616.82,2598.12 5616.82,2639.62 J23.30@5620.24,2643.03
PORTE_TX3N: J23.28 MC3.4 | length 2185.9
  L1-TOP w4.2: MC3.4@5350.8,1053.17 5354.35,1056.71 5393.42,1056.71 5418.11,1081.4 5418.11,1166.14 5437.01,1185.04 5637.8,1185.04 5908.73,1455.97 5908.73,2109.74 5908.73,2227.26 5688.48,2447.5 5688.48,2501.37 5711.95,2524.84 5718.95,2524.84 v1(5721.59,2527.48)
  L8-BOT w4.2: v1(5658.2,2687.72) 5658.2,2683.98 5663.15,2679.03 5663.15,2527.69 5675.88,2514.96 5702.07,2514.96 5713.63,2526.52 5720.63,2526.52 v1(5721.59,2527.48)
PORTE_TX3P: J23.26 MC3.2 | length 2185.9
  L1-TOP w4.2: MC3.2@5350.8,1072.85 5354.35,1069.31 5388.21,1069.31 5405.51,1086.61 5405.51,1105.58 5405.51,1107.68 ccw(c5400.67,1107.68) 5400.67,1112.52 5385.32,1112.52 cw(c5385.32,1117.36) 5380.48,1117.36 5380.48,1131.88 cw(c5385.32,1131.88) 5385.32,1136.72 5400.67,1136.72 ccw(c5400.67,1141.56) 5405.51,1141.56 5405.51,1157.45 5405.51,1171.36 5431.79,1197.64 5632.58,1197.64 5896.13,1461.19 5896.13,2222.04 5675.88,2442.29 5675.88,2506.59 5703.04,2533.75 5703.04,2540.75 v1(5705.68,2543.39)
  L8-BOT w4.2: v1(5680.7,2687.72) 5680.7,2683.98 5675.75,2679.03 5675.75,2532.91 5681.1,2527.56 5696.85,2527.56 5704.72,2535.43 5704.72,2542.43 v1(5705.68,2543.39)
PORTF_C2P_CLKN: J8.36 MC1.136 | length 4262.3
  L1-TOP w4.2: MC1.136@4655.53,1315.37 4651.98,1318.91 4651.98,1360.65 4669.29,1377.95 4725.9,1377.95 4728.36,1375.49 v1(4728.36,1373)
  L3-SIG w4.25: v1(4728.36,1373) 4732.08,1373 4737.01,1377.93 4763.38,1377.93 cw(c4763.38,1373.08) 4768.23,1373.08 4768.23,1365.3 ccw(c4773.08,1365.3) 4773.08,1360.45 4787.63,1360.45 ccw(c4787.63,1365.3) 4792.48,1365.3 4792.48,1373.08 cw(c4797.33,1373.08) 4797.33,1377.93 4811.88,1377.93 cw(c4811.88,1373.08) 4816.73,1373.08 4816.73,1371.01 ccw(c4821.58,1371.01) 4821.58,1366.16 4836.13,1366.16 ccw(c4836.13,1371.01) 4840.98,1371.01 4840.98,1373.08 cw(c4845.83,1373.08) 4845.83,1377.93 4877.95,1377.93 5004.09,1377.93 5069.82,1443.67 5069.82,1471.02 5193.1,1594.3 5227.33,1628.53 cw(c5230.76,1625.1) 5234.2,1628.51 ; 5234.23,1628.48 ccw(c5246.56,1640.9) 5258.93,1628.53 5269.22,1638.82 ccw(c5256.85,1651.19) 5269.22,1663.56 5232.24,1700.55 cw(c5235.66,1703.98) 5232.24,1707.41 5242.52,1717.7 cw(c5245.95,1714.27) 5249.38,1717.7 5288.21,1678.87 ccw(c5300.62,1691.21) 5312.99,1678.84 5323.28,1689.13 ccw(c5310.91,1701.5) 5325.13,1711.69 5325.13,1712.02 5279.97,1757.19 cw(c5283.41,1760.6) 5279.98,1764.03 5290.27,1774.32 cw(c5293.7,1770.89) 5297.15,1774.3 ; 5297.16,1774.29 5340.4,1731.05 ccw(c5352.8,1743.4) 5365.18,1731.02 5375.46,1741.31 ccw(c5363.09,1753.68) 5377.32,1763.88 5377.32,1764.21 5332.15,1809.37 cw(c5335.6,1812.78) 5332.17,1816.21 5342.46,1826.5 cw(c5345.89,1823.07) 5349.33,1826.49 ; 5349.35,1826.47 5392.58,1783.24 ccw(c5404.99,1795.58) 5417.36,1783.21 5427.65,1793.49 ccw(c5415.27,1805.87) 5429.5,1816.06 5429.5,1816.39 5425.78,1820.12 cw(c5429.2,1823.55) 5425.78,1826.98 5431.75,1832.95 5441.39,1842.59 5441.39,2120.33 5498.31,2177.24 6090.63,2177.24 6478.91,2565.52 7240.11,2565.52 7397.03,2722.44 7574.8,2722.44 7592.26,2704.99 7592.26,2690.21 7589.77,2687.72 v1(7587.33,2687.72)
PORTF_C2P_CLKP: J8.34 MC1.134 | length 4262.3
  L1-TOP w4.2: MC1.134@4635.84,1315.37 4639.39,1318.91 4639.39,1365.87 4664.07,1390.55 4725.9,1390.55 4725.9,1393.04 v1(4728.36,1395.5)
  L3-SIG w4.25: v1(4728.36,1395.5) 4732.08,1395.5 4737.01,1390.58 4998.85,1390.58 5057.17,1448.91 5057.17,1476.26 5184.16,1603.25 5218.38,1637.47 cw(c5230.76,1625.1) 5240.95,1639.32 5241.28,1639.32 5243.13,1637.47 ccw(c5246.56,1640.9) 5249.99,1637.47 5260.28,1647.76 ccw(c5256.85,1651.19) 5260.28,1654.62 5223.29,1691.61 cw(c5235.66,1703.98) 5223.29,1716.35 5233.58,1726.64 cw(c5245.95,1714.27) 5258.33,1726.64 5297.04,1687.93 5297.21,1687.76 ccw(c5300.62,1691.21) 5304.05,1687.78 5314.34,1698.07 ccw(c5310.91,1701.5) 5314.32,1704.94 ; 5314.31,1704.96 5271.07,1748.2 cw(c5283.41,1760.6) 5271.04,1772.97 5281.33,1783.26 cw(c5293.7,1770.89) 5303.89,1785.12 5304.22,1785.12 5349.39,1739.95 ccw(c5352.8,1743.4) 5356.23,1739.97 5366.52,1750.26 ccw(c5363.09,1753.68) 5366.51,1757.13 ; 5366.49,1757.14 5323.25,1800.38 cw(c5335.6,1812.78) 5323.22,1825.16 5333.51,1835.45 cw(c5345.89,1823.07) 5356.08,1837.3 5356.41,1837.3 5401.58,1792.13 ccw(c5404.99,1795.58) 5408.42,1792.15 5418.7,1802.44 ccw(c5415.27,1805.87) 5418.69,1809.31 5416.83,1811.17 cw(c5429.2,1823.55) 5416.83,1835.92 5422.81,1841.9 5428.74,1847.83 5428.74,2125.57 5493.07,2189.89 6085.39,2189.89 6473.67,2578.17 7234.87,2578.17 7391.79,2735.09 7580.04,2735.09 7604.91,2710.23 7604.91,2690.21 7607.4,2687.72 v1(7609.83,2687.72)
PORTF_P2C_CLKN: J8.35 MC1.146 | length 4262.6
  L1-TOP w4.2: v1(4696.03,1165.01) 4696.03,1161.27 4700.98,1156.32 4700.98,1146.52 4714.56,1132.94 4747.56,1132.94 4766.91,1152.29 4766.91,1242.93 4750.41,1259.43 4750.41,1311.83 MC1.146@4753.95,1315.37
  L3-SIG w4.25: v1(4696.03,1165.01) 4696.03,1168.73 4700.96,1173.65 4700.96,1261.64 4671.49,1291.1 4671.49,1425.29 4726.37,1480.17 4881.47,1480.17 5386.84,1985.54 5386.84,2142.92 5530.33,2286.41 5816.99,2286.41 5947.33,2416.75 6253,2416.75 6456.31,2620.07 6602.36,2620.07 6719.24,2620.07 ccw(c6719.24,2624.92) 6724.09,2624.92 cw(c6741.59,2624.92) 6741.59,2642.42 6756.14,2642.42 cw(c6756.14,2624.92) 6773.64,2624.92 ccw(c6778.49,2624.92) 6778.49,2620.07 6793.04,2620.07 ccw(c6793.04,2624.92) 6797.89,2624.92 6797.89,2628.38 cw(c6815.39,2628.38) 6815.39,2645.88 6829.94,2645.88 cw(c6829.94,2628.38) 6847.44,2628.38 6847.44,2624.92 ccw(c6852.29,2624.92) 6852.29,2620.07 6897.64,2620.07 7217.51,2620.07 7407.34,2809.89 7532.34,2809.89 7592.26,2869.82 7592.26,2911.21 7589.77,2913.7 v1(7587.33,2913.7)
PORTF_P2C_CLKP: J8.33 MC1.144 | length 4262.6
  L1-TOP w4.2: v1(4718.53,1165.01) 4718.53,1161.27 4713.58,1156.32 4713.58,1151.74 4719.78,1145.54 4742.34,1145.54 4754.31,1157.51 4754.31,1237.72 4737.81,1254.21 4737.81,1311.83 MC1.144@4734.27,1315.37
  L3-SIG w4.25: v1(4718.53,1165.01) 4718.53,1168.73 4713.61,1173.65 4713.61,1184.96 4713.61,1211.33 cw(c4718.46,1211.33) 4718.46,1216.18 4733.8,1216.18 ccw(c4733.8,1221.03) 4738.65,1221.03 4738.65,1235.58 ccw(c4733.8,1235.58) 4733.8,1240.43 4718.46,1240.43 cw(c4718.46,1245.28) 4713.61,1245.28 4713.61,1254.78 4713.61,1266.88 4684.14,1296.34 4684.14,1420.05 4731.61,1467.52 4886.71,1467.52 5399.49,1980.3 5399.49,2137.68 5535.57,2273.76 5822.23,2273.76 5952.57,2404.1 6258.23,2404.1 6461.55,2607.42 6602.36,2607.42 6719.24,2607.42 ccw(c6719.24,2624.92) 6736.74,2624.92 cw(c6741.59,2624.92) 6741.59,2629.77 6756.14,2629.77 cw(c6756.14,2624.92) 6760.99,2624.92 ccw(c6778.49,2624.92) 6778.49,2607.42 6793.04,2607.42 ccw(c6793.04,2624.92) 6810.54,2624.92 6810.54,2628.38 cw(c6815.39,2628.38) 6815.39,2633.23 6829.94,2633.23 cw(c6829.94,2628.38) 6834.79,2628.38 6834.79,2624.92 ccw(c6852.29,2624.92) 6852.29,2607.42 6897.64,2607.42 7222.75,2607.42 7412.57,2797.24 7537.57,2797.24 7604.91,2864.58 7604.91,2911.21 7607.4,2913.7 v1(7609.83,2913.7)
PORTF_REFCLKN: J8.15 MC3.88 | length 5897.7
  L1-TOP w4.2: v1(7244.09,2322.83) 7246.73,2325.48 7253.74,2325.48 7325.98,2397.72 7325.98,2657.34 7406.65,2738 7769.38,2738 7820.01,2788.63 7874.77,2788.63 7887.56,2801.42 7887.56,2823.97 7887.43,2824.1 7887.43,2865.6 J8.15@7884.01,2869.02
  L8-BOT w4.2: v1(5380.17,-582.19) 5376.44,-582.19 5371.4,-577.15 5236.37,-577.15 5115.67,-456.45 5115.67,999.75 5158.53,1042.61 5158.53,1257.5 5158.53,1392.65 5117.32,1433.86 5117.32,1536.72 5144.23,1563.63 5199.96,1563.63 5365.85,1729.52 5855.85,1729.52 6470.28,2343.95 7151.81,2343.95 7192.6,2303.15 7231.41,2303.15 7241.45,2313.19 7241.45,2320.19 v1(7244.09,2322.83)
PORTF_REFCLKP: J8.13 MC3.86 | length 5897.7
  L1-TOP w4.2: v1(7260,2306.92) 7262.64,2309.57 7262.64,2316.57 7338.58,2392.5 7338.58,2543.31 7338.58,2569.61 cw(c7343.42,2569.61) 7343.42,2574.45 7348.34,2574.45 ccw(c7348.34,2579.29) 7353.18,2579.29 7353.18,2593.81 ccw(c7348.34,2593.81) 7348.34,2598.65 7343.42,2598.65 cw(c7343.42,2603.49) 7338.58,2603.49 7338.58,2636.71 7338.58,2652.12 7411.87,2725.4 7774.6,2725.4 7825.23,2776.03 7879.99,2776.03 7900.16,2796.2 7900.16,2823.97 7900.29,2824.1 7900.29,2865.6 J8.13@7903.7,2869.02
  L8-BOT w4.2: v1(5380.17,-559.51) 5376.44,-559.51 5371.4,-564.55 5241.59,-564.55 5128.27,-451.23 5128.27,994.53 5171.13,1037.39 5171.13,1047.83 5171.13,1397.87 5129.92,1439.08 5129.92,1531.5 5149.45,1551.03 5205.18,1551.03 5214.09,1559.94 5371.07,1716.92 5861.07,1716.92 6475.5,2331.35 7146.59,2331.35 7178.47,2299.46 7187.38,2290.55 7236.63,2290.55 7250.36,2304.28 7257.36,2304.28 v1(7260,2306.92)
PORTF_RX0N: J8.7 MC3.103 | length 7011.9
  L8-BOT w4.2: v1(5623.48,-818.41) 5619.75,-818.41 5614.7,-813.37 5600.99,-813.37 5484.44,-929.92 5230.69,-929.92 4862.2,-561.44 4862.2,1104.74 4905.06,1147.6 4905.06,1282.52 4861.27,1326.32 4825.6,1326.32 4777.92,1373.99 4777.92,1611.4 4988.97,1822.45 5104.09,1822.45 5261.96,1980.32 5751.97,1980.32 6366.4,2594.74 7199.48,2594.74 7412.61,2807.88 7468.5,2807.88 7516.54,2807.88 7582.7,2874.04 7990.34,2874.04 8005.67,2889.37 8005.67,2905.02 8000.72,2909.97 v1(8000.72,2913.7)
PORTF_RX0P: J8.5 MC3.101 | length 7011.9
  L8-BOT w4.2: v1(5623.48,-795.73) 5619.75,-795.73 5614.7,-800.77 5595.77,-800.77 5564.41,-832.13 5545.82,-850.73 cw(c5542.39,-847.31) 5538.97,-850.73 5535.5,-847.25 ccw(c5532.08,-850.68) 5528.65,-847.25 5518.39,-857.52 ccw(c5521.81,-860.94) 5518.39,-864.37 5521.86,-867.84 cw(c5518.44,-871.26) 5521.86,-874.68 5501.86,-894.69 5479.22,-917.32 5235.9,-917.32 4874.8,-556.22 4874.8,1099.53 4917.66,1142.38 4917.66,1256.42 4917.66,1287.74 4866.49,1338.92 4830.82,1338.92 4790.52,1379.21 4790.52,1606.18 4994.19,1809.85 5109.31,1809.85 5118.22,1818.75 5267.18,1967.72 5757.19,1967.72 6371.62,2582.14 7204.7,2582.14 7417.83,2795.28 7468.5,2795.28 7521.76,2795.28 7587.92,2861.44 7995.56,2861.44 8018.27,2884.15 8018.27,2905.02 8023.22,2909.97 v1(8023.22,2913.7)
PORTF_RX1N: J8.11 MC3.99 | length 6747.6
  L8-BOT w4.2: v1(5564.74,-759.36) 5561.01,-759.36 5555.96,-754.32 5517.34,-754.32 5450.67,-820.98 5450.67,-846.68 5418.6,-878.74 5239.53,-878.74 4904.65,-543.86 4904.65,1087.16 4947.51,1130.02 4947.51,1304.04 4877.53,1374.02 4844.39,1374.02 4821,1397.4 4821,1595.36 5006.28,1780.65 5121.41,1780.65 5279.28,1938.52 5769.28,1938.52 6383.71,2552.94 7216.8,2552.94 7388.1,2724.25 7463.29,2724.25 7511.65,2724.25 7575.59,2788.19 7932.05,2788.19 7946.61,2802.76 7946.61,2815.65 7941.66,2820.6 v1(7941.66,2824.33) v1@7943.07,2822.92
PORTF_RX1P: J8.9 MC3.97 | length 6745.6
  L8-BOT w4.2: v1(5564.74,-736.67) 5561.01,-736.67 5555.96,-741.72 5512.12,-741.72 5499.52,-754.32 5480.92,-772.91 cw(c5477.5,-769.49) 5474.08,-772.91 5470.6,-769.44 ccw(c5467.18,-772.86) 5463.76,-769.44 5453.49,-779.71 ccw(c5456.91,-783.13) 5453.49,-786.55 5456.97,-790.02 cw(c5453.54,-793.45) 5456.96,-796.87 5444.06,-809.78 5438.07,-815.76 5438.07,-841.46 5413.39,-866.14 5244.75,-866.14 4917.25,-538.64 4917.25,1081.94 4960.11,1124.8 4960.11,1256.42 4960.11,1309.26 4882.75,1386.62 4849.6,1386.62 4833.6,1402.62 4833.6,1590.15 5011.5,1768.05 5126.63,1768.05 5135.54,1776.95 5284.5,1925.92 5774.5,1925.92 6388.93,2540.34 7222.02,2540.34 7393.32,2711.65 7516.87,2711.65 7580.81,2775.59 7937.27,2775.59 7959.21,2797.54 7959.21,2815.65 7964.16,2820.6 v1(7964.16,2824.33)
PORTF_RX2N: J8.31 MC3.95 | length 5933.1
  L1-TOP w4.2: v1(7071.3,2279.09) 7073.94,2281.73 7080.94,2281.73 7089.76,2290.55 7089.76,2377.16 7207.87,2495.27 7207.87,2750.77 7300.41,2843.31 7461.64,2843.31 7493.18,2811.77 7645.92,2811.77 7651.34,2817.19 7651.34,2823.97 7651.21,2824.1 7651.21,2865.6 J8.31@7647.79,2869.02
  L8-BOT w4.2: v1(5623.48,-700.3) 5619.75,-700.3 5614.7,-695.26 5453.03,-695.26 5436.6,-678.83 5436.6,-535.02 5410.94,-509.36 5227.7,-509.36 5157.47,-439.14 5157.47,982.44 5200.33,1025.3 5200.33,1504.88 5383.16,1687.72 5873.17,1687.72 6487.6,2302.15 6989.05,2302.15 7028.78,2262.41 7061.62,2262.41 7073.06,2273.85 7073.06,2277.33 v1(7071.3,2279.09)
PORTF_RX2P: J8.29 MC3.93 | length 5933.1
  L1-TOP w4.2: v1(7087.21,2263.18) 7089.85,2265.82 7089.85,2272.82 7102.36,2285.33 7102.36,2371.94 7220.47,2490.06 7220.47,2738.17 7220.47,2745.55 7233.67,2758.75 cw(c7237.09,2755.32) 7240.51,2758.75 7243.99,2755.27 ccw(c7247.41,2758.69) 7250.83,2755.27 7261.1,2765.54 ccw(c7257.68,2768.96) 7261.1,2772.38 7257.62,2775.86 cw(c7261.05,2779.28) 7257.62,2782.7 7282.74,2807.81 7305.63,2830.71 7456.42,2830.71 7487.97,2799.17 7651.13,2799.17 7663.94,2811.97 7663.94,2823.97 7664.07,2824.1 7664.07,2865.6 J8.29@7667.48,2869.02
  L8-BOT w4.2: v1(5623.48,-677.62) 5619.75,-677.62 5614.7,-682.66 5458.25,-682.66 5449.2,-673.61 5449.2,-529.81 5416.15,-496.76 5232.92,-496.76 5170.07,-433.92 5170.07,977.22 5212.93,1020.08 5212.93,1032.68 5212.93,1256.42 5212.93,1499.66 5388.38,1675.12 5878.39,1675.12 6492.82,2289.55 6983.83,2289.55 7023.56,2249.81 7054.24,2249.81 7066.84,2249.81 7081.97,2264.94 7083.73,2263.18 v1(7087.21,2263.18)
PORTF_RX3N: J8.27 MC3.91 | length 5767.4
  L1-TOP w4.2: v1(7126.42,2223.97) 7129.06,2226.61 7136.06,2226.61 7161.57,2252.12 7161.57,2371.03 7262.99,2472.44 7262.99,2653.46 7395.04,2785.5 7468.5,2785.5 7686.9,2785.5 7710.39,2809 7710.39,2823.97 7710.26,2824.1 7710.26,2865.6 J8.27@7706.85,2869.02
  L8-BOT w4.2: v1(5564.74,-641.25) 5561.01,-641.25 5555.96,-636.21 5523.9,-636.21 5498.24,-610.55 5498.24,-470.68 5488.19,-460.63 5238.08,-460.63 5199.27,-421.82 5199.27,965.13 5242.13,1007.98 5242.13,1487.57 5400.48,1645.92 5890.48,1645.92 6504.91,2260.35 6966.45,2260.35 7019.08,2207.72 7117.17,2207.72 7128.18,2218.73 7128.18,2222.21 v1(7126.42,2223.97)
PORTF_RX3P: J8.25 MC3.89 | length 5767.4
  L1-TOP w4.2: v1(7142.33,2208.06) 7144.97,2210.7 7144.97,2217.7 7174.17,2246.91 7174.17,2365.81 7209.3,2400.93 7227.9,2419.53 cw(c7231.32,2416.11) 7234.74,2419.53 7238.22,2416.06 ccw(c7241.64,2419.48) 7245.06,2416.06 7255.33,2426.33 ccw(c7251.91,2429.75) 7255.33,2433.17 7251.86,2436.64 cw(c7255.28,2440.07) 7251.86,2443.49 7266.7,2458.33 7275.59,2467.22 7275.59,2648.24 7400.26,2772.9 7468.5,2772.9 7692.12,2772.9 7722.99,2803.78 7722.99,2823.97 7723.12,2824.1 7723.12,2865.6 J8.25@7726.53,2869.02
  L8-BOT w4.2: v1(5564.74,-618.56) 5561.01,-618.56 5555.96,-623.61 5529.12,-623.61 5510.84,-605.33 5510.84,-465.46 5493.41,-448.03 5243.3,-448.03 5211.87,-416.6 5211.87,959.91 5254.73,1002.76 5254.73,1015.36 5254.73,1256.42 5254.73,1482.35 5405.7,1633.32 5895.7,1633.32 6510.13,2247.75 6961.24,2247.75 7013.86,2195.12 7109.79,2195.12 7122.39,2195.12 7137.09,2209.82 7138.85,2208.06 v1(7142.33,2208.06)
PORTF_S0: J8.14 MC1.152 | length 4304.3
  L1-TOP w4.5: v1(4812.93,1239.76) v1@4813.01,1239.84 ; v1@4813.01,1239.76 v1@4813.01,1239.84 ; MC1.152@4813.08,1315.45 MC1.152@4813.01,1315.37 v1@4813.01,1239.84 ; v1(7903.7,2572.01) J8.14@7903.7,2643.03
  L3-SIG w4.6: v1(4812.93,1239.76) 4812.93,1288.35 4845.44,1320.87 5079.65,1320.87 5233.14,1474.35 5233.14,1535.39 5571.76,1874.02 5582.68,1874.02 5584.98,1874.02 ccw(c5584.98,1878.94) 5589.9,1878.94 5589.9,1887.24 cw(c5594.82,1887.24) 5594.82,1892.16 5609.58,1892.16 cw(c5609.58,1887.24) 5614.5,1887.24 5614.5,1853.94 ccw(c5619.42,1853.94) 5619.42,1849.02 5634.18,1849.02 ccw(c5634.18,1853.94) 5639.1,1853.94 5639.1,1894.1 cw(c5644.02,1894.1) 5644.02,1899.02 5658.78,1899.02 cw(c5658.78,1894.1) 5663.7,1894.1 5663.7,1853.94 ccw(c5668.62,1853.94) 5668.62,1849.02 5683.38,1849.02 ccw(c5683.38,1853.94) 5688.3,1853.94 5688.3,1894.1 cw(c5693.22,1894.1) 5693.22,1899.02 5707.98,1899.02 cw(c5707.98,1894.1) 5712.9,1894.1 5712.9,1853.94 ccw(c5717.82,1853.94) 5717.82,1849.02 5732.58,1849.02 ccw(c5732.58,1853.94) 5737.5,1853.94 5737.5,1894.1 cw(c5742.42,1894.1) 5742.42,1899.02 5757.18,1899.02 cw(c5757.18,1894.1) 5762.1,1894.1 5762.1,1853.94 ccw(c5767.02,1853.94) 5767.02,1849.02 5781.78,1849.02 ccw(c5781.78,1853.94) 5786.7,1853.94 5786.7,1894.1 cw(c5791.62,1894.1) 5791.62,1899.02 5806.38,1899.02 cw(c5806.38,1894.1) 5811.3,1894.1 5811.3,1866.05 ccw(c5816.22,1866.05) 5816.22,1861.13 5830.98,1861.13 ccw(c5830.98,1866.05) 5835.9,1866.05 5835.9,1869.1 cw(c5840.82,1869.1) 5840.82,1874.02 5901.99,1874.02 5976.82,1874.02 6415.74,2312.94 6950.66,2312.94 7052.22,2414.5 7805.92,2414.5 7903.77,2512.36 v1@7903.77,2572.08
